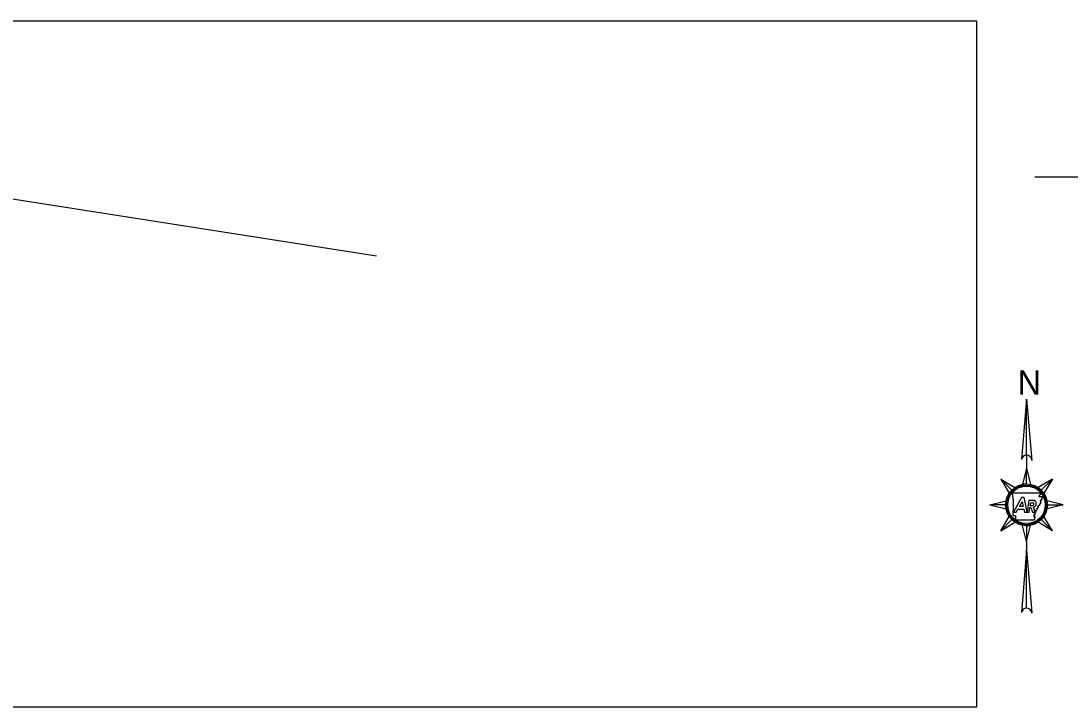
# Model space of a CAD drawing. Extents: x 1096785 to 1382432, y 216169 to 341661.
# Drawn here: x 1178500 to 1204876, y 267368 to 284619 of the extents above; entities that cross this region are included whole.
import ezdxf

# ---------------------------------------------------------------- set-up
doc = ezdxf.new("R2010")
doc.units = 0
for name, color, linetype in [('1', 7, 'Continuous'), ('15', 7, 'Continuous'), ('7', 7, 'Continuous')]:
    doc.layers.add(name, color=color, linetype=linetype)

msp = doc.modelspace()

# ---------------------------------------------------------------- linework, layer by layer
at = {"layer": '1'}
for p, q in [((1169119.475087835, 281573.9332302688), (1187439.3608533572, 278716.3904419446)), ((1203994.739436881, 280695.88328606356), (1218829.6940148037, 280695.88328606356))]:
    msp.add_line(p, q, dxfattribs=at)
at = {"layer": '15'}
for p, q in [((1203782.268836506, 275106.50879252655), (1203652.922527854, 273593.1569813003)), ((1203782.268836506, 275106.50879252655), (1203913.518836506, 273570.88379252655)), ((1203782.268836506, 273702.13379252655), (1203782.268836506, 275106.50879252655)), ((1203782.268836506, 273702.13379252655), (1203782.268836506, 273370.33467056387)), ((1203913.518836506, 273570.88379252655), (1203911.6151451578, 273593.1569813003)), ((1203782.268836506, 273370.33467056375), (1203680.0343561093, 272966.53429044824)), ((1203782.268836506, 272976.58467056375), (1203782.268836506, 273370.33467056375)), ((1203411.0377763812, 272822.81573068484), (1203132.6144812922, 273101.2390257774)), ((1203132.6144812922, 273101.2390257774), (1203345.853773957, 272743.41834439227)), ((1204431.9231917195, 273101.2390257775), (1204074.1025103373, 272887.9997331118)), ((1204153.4998966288, 272822.8157306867), (1204431.9231917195, 273101.2390257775)), ((1204701.018836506, 272451.58467056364), (1204297.2184563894, 272553.81915095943)), ((1203257.268836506, 272451.58467056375), (1202863.518836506, 272451.58467056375)), ((1202863.518836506, 272451.58467056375), (1203267.3192166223, 272349.3501901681)), ((1204307.268836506, 272451.58467056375), (1204701.018836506, 272451.58467056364)), ((1203411.3129541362, 272080.07863651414), (1203132.6144812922, 271801.9303153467)), ((1203132.6144812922, 271801.9303153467), (1203490.4351626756, 272015.16960801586)), ((1203782.268836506, 271532.83467056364), (1203884.5033169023, 271936.63505067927)), ((1204153.4998966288, 272080.3536104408), (1204431.9231917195, 271801.9303153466)), ((1204153.4998966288, 272080.3536104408), (1204431.9231917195, 271801.9303153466)), ((1204431.9231917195, 271801.9303153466), (1204218.683899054, 272159.7509967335)), ((1203782.268836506, 271926.58467056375), (1203782.268836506, 271532.83467056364)), ((1203782.268836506, 271532.83467056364), (1203782.268836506, 271313.3837925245)), ((1203782.268836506, 271313.38379252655), (1203652.7995840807, 269746.8058381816)), ((1203782.268836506, 271313.38379252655), (1203911.7380889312, 269746.8058381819)), ((1203782.268836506, 269856.50879252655), (1203782.268836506, 271313.38379252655)), ((1203913.518836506, 269725.25879252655), (1203911.7380889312, 269746.8058381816))]:
    msp.add_line(p, q, dxfattribs=at)
for points in [[(1203782.268836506, 273370.33467056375), (1203884.5033169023, 272966.53429044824)], [(1203132.6144812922, 273101.2390257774), (1203490.435162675, 272887.9997331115)], [(1204431.9231917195, 273101.2390257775), (1204218.6838990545, 272743.41834439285)], [(1203423.8189762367, 272752.09738259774), (1203628.6294798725, 272751.99966309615), (1203808.5226136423, 272752.40534711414), (1204020.6156765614, 272755.58123113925), (1204118.8695142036, 272757.94722772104)], [(1203423.8189762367, 272752.09738259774), (1203450.0142738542, 272541.49555531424), (1203446.4085333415, 272433.6176597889)], [(1202863.518836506, 272451.58467056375), (1203267.3192166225, 272553.81915096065)], [(1203987.6870217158, 272557.19032146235), (1203844.101783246, 272557.1903214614), (1203795.4400305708, 272277.4364814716), (1203719.3881850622, 272633.50112970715), (1203657.9441271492, 272633.50112970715), (1203451.1812406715, 272267.65591283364)], [(1203603.2809752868, 272411.25397802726), (1203670.9099577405, 272530.91636121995), (1203696.4686452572, 272411.25397802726), (1203603.2809752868, 272411.25397802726)], [(1203936.8481913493, 272427.4251297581), (1203875.2653858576, 272427.4251297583), (1203888.8550725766, 272505.55151926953), (1203956.2779650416, 272505.5515192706)], [(1204088.5679667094, 272659.0817359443), (1204184.801997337, 272663.8403798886)], [(1203446.4085333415, 272433.6176597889), (1203438.6921005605, 272197.82492770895)], [(1203451.1812406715, 272267.65591283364), (1203522.1243847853, 272267.65591283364), (1203565.5095687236, 272344.4214402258), (1203710.743406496, 272344.4214402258), (1203727.13975491, 272267.65591283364), (1203847.4743459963, 272267.65591283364), (1203867.713570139, 272384.010140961), (1203892.5938087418, 272384.010140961), (1203935.5005806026, 272267.6559128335), (1203998.5718803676, 272267.65591283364), (1203953.3761990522, 272390.21718664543)], [(1204701.018836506, 272451.58467056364), (1204297.2184563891, 272349.3501901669)], [(1203132.6144812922, 271801.9303153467), (1203345.853773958, 272159.75099673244)], [(1203508.726391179, 272177.6754611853), (1203508.9736842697, 272074.9500488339), (1203973.3886202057, 272074.2645316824)], [(1203782.268836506, 271532.83467056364), (1203680.0343561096, 271936.6350506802)], [(1204431.9231917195, 271801.9303153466), (1204074.1025103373, 272015.16960801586)]]:
    msp.add_lwpolyline(points, dxfattribs=at)
for radius in [525.0000000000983, 498.7500000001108, 472.5000000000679]:
    msp.add_circle((1203782.268836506, 272451.58467056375), radius, dxfattribs=at)
for centre, radius, start, end in [((1203782.268836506, 273570.88379252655), 131.25, 89.99999999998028, 170.22959486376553), ((1203782.268836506, 273570.88379252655), 131.25, 9.7704051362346, 89.99999999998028), ((1203782.268836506, 272451.58467056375), 525.0000000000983, 135.000000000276, 146.22908827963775), ((1203782.268836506, 272451.58467056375), 525.0000000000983, 89.99999999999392, 101.22908827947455), ((1203782.268836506, 272451.58467056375), 525.0000000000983, 44.999999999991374, 56.22908827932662), ((1203782.268836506, 272451.58467056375), 525.0000000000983, 0, 11.229088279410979), ((1203782.268836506, 272451.58467056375), 525.0000000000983, 180, 191.22908827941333), ((1203782.268836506, 272451.58467056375), 525.0000000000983, 225.0424551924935, 236.22908827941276), ((1203782.268836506, 272451.58467056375), 525.0000000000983, 269.99999999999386, 281.22908827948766), ((1203782.268836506, 272451.58467056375), 525.0000000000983, 315.0000000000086, 326.2290882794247), ((1203782.268836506, 269725.25879252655), 131.25, 89.9999999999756, 170.55109660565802), ((1203782.268836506, 269725.25879252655), 131.25, 9.448903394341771, 89.99999999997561)]:
    msp.add_arc(centre, radius, start, end, dxfattribs=at)
for centre, major_axis, ratio, start_param, end_param in [((1203922.0879920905, 272472.59841424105), (1.5880278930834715e-10, 47.53230592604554), 0.9980982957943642, 3.457965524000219, 5.478416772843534), ((1203934.3064864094, 272481.1759419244), (1.931741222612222e-10, 92.94372588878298), 0.9980982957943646, 3.3486344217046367, 5.670060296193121)]:
    msp.add_ellipse(centre, major_axis=major_axis, ratio=ratio, start_param=start_param, end_param=end_param, dxfattribs=at)
for points in [[(1204118.8695142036, 272757.94722772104), (1204119.584739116, 272752.40534711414), (1204121.2950595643, 272749.48412605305), (1204121.580853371, 272744.102150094), (1204123.8168567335, 272741.8012998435), (1204127.4255588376, 272739.5907661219), (1204130.6921968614, 272735.91888155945), (1204131.5332895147, 272731.68733072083), (1204130.477481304, 272727.1463347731), (1204130.3205168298, 272722.1419114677), (1204129.7296788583, 272717.8777874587), (1204128.9492988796, 272714.0489594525), (1204125.8055670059, 272710.78572010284), (1204123.104593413, 272708.5115206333), (1204120.3947350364, 272705.83904013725), (1204118.37196644, 272703.1621178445), (1204115.1704834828, 272700.0217681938), (1204111.8683063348, 272696.88141853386), (1204109.1317936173, 272694.1097379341), (1204106.455993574, 272690.56370425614), (1204105.2106433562, 272686.6741716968), (1204102.4415531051, 272683.8462283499), (1204100.0174885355, 272681.32476890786), (1204096.9359501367, 272677.8409203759), (1204095.5706553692, 272674.5421466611), (1204092.7067941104, 272670.56377819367), (1204091.9589916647, 272666.80305771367), (1204090.0606100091, 272663.68639763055), (1204089.902164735, 272663.1563433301)], [(1204135.0501822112, 272541.90420053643), (1204135.547729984, 272538.3581668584), (1204133.366516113, 272534.3102102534), (1204132.5283850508, 272530.4547314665), (1204132.9667009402, 272526.4112166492), (1204128.9492988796, 272524.32801440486), (1204125.3405967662, 272521.7739817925), (1204127.4255588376, 272518.7580024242), (1204131.2859964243, 272516.08256072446), (1204135.0501822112, 272513.8764687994), (1204137.3839181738, 272511.60226932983), (1204138.0665655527, 272506.4734757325), (1204138.8173295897, 272503.20283339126), (1204139.9027537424, 272498.601132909), (1204140.3677239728, 272495.48743402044), (1204138.287204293, 272491.6956209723), (1204135.547729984, 272490.8235483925), (1204132.716446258, 272491.7222717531), (1204129.5120017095, 272492.0361586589), (1204126.8687792, 272489.5176604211), (1204124.8445298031, 272486.0308506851), (1204123.104593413, 272482.3323153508), (1204121.580853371, 272479.37704051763), (1204120.1504035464, 272476.07530560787), (1204117.5634513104, 272472.256841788), (1204114.019904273, 272471.6646023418), (1204110.0025022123, 272470.5704399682), (1204107.513282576, 272467.8076429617), (1204107.9812144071, 272463.0786109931), (1204110.2527568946, 272460.0270972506), (1204112.023790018, 272456.0487287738), (1204113.2099083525, 272452.62262358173), (1204112.5864928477, 272448.33036820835), (1204110.8110173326, 272445.12487220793), (1204108.6372074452, 272443.2918911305), (1204107.513282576, 272439.15213740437), (1204105.8962523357, 272436.1687311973), (1204104.3399347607, 272435.0760494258), (1204101.415360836, 272435.3914169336), (1204098.0569134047, 272436.1391192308), (1204095.3174390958, 272435.79413975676), (1204092.7067941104, 272434.3609202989), (1204089.902164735, 272435.23299287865), (1204087.1997103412, 272438.25193345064), (1204084.8333968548, 272440.6149688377), (1204082.2494062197, 272441.4529876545), (1204079.60470291, 272440.08491452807), (1204079.2330228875, 272435.9510832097), (1204080.5405665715, 272431.56258891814), (1204081.6289523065, 272425.68757362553), (1204080.5405665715, 272422.231856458), (1204080.1333474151, 272416.3849725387)], [(1204184.801997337, 272663.8403798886), (1204189.1214819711, 272659.3911810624), (1204190.8021864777, 272655.57123664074), (1204193.7563763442, 272653.51468516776), (1204196.900108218, 272652.3953526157), (1204199.2338441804, 272649.40898521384), (1204200.9145486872, 272646.2701161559), (1204200.0719752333, 272643.4392116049), (1204196.4321763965, 272643.18899043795), (1204192.5125069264, 272642.50347327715), (1204188.7808986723, 272642.7240824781), (1204185.6667827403, 272640.07825275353), (1204188.5336055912, 272636.74690587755), (1204192.2030203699, 272633.45109336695), (1204193.1684999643, 272630.18489282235), (1204191.1146346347, 272626.8254145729), (1204187.1001941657, 272625.0531380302), (1204183.11833123, 272623.5592140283), (1204179.6044001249, 272620.53879286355), (1204177.953311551, 272617.65014496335), (1204174.1565482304, 272616.3131644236), (1204170.0221632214, 272615.159778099), (1204166.505270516, 272614.78962844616), (1204162.3930974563, 272613.9767798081), (1204158.476389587, 272612.0534822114), (1204156.9200720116, 272608.90721016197), (1204157.358387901, 272604.05824969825), (1204157.2310393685, 272599.2063280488), (1204161.3698667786, 272597.5228874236), (1204165.104436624, 272597.3689051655), (1204168.618367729, 272595.5951480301), (1204168.2141101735, 272592.82642862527), (1204165.6301195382, 272589.12493209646), (1204162.3930974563, 272586.4494903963), (1204159.3470981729, 272585.0784560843), (1204156.3603307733, 272582.2830859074), (1204157.358387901, 272579.73201449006), (1204160.1274781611, 272577.95085436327), (1204161.8052210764, 272574.96744815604), (1204161.5875439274, 272572.44598872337), (1204158.6318732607, 272570.45902537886), (1204155.2423290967, 272571.23633965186), (1204152.9085931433, 272574.44035505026), (1204150.1705996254, 272575.34055900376), (1204147.6488024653, 272576.4939453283), (1204145.0381574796, 272574.8149465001), (1204145.0381574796, 272571.23633965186), (1204143.8846166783, 272567.44008480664), (1204144.8175187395, 272564.3619202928), (1204145.9384820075, 272560.31692488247), (1204145.7800367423, 272557.3290768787), (1204144.8175187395, 272552.91245122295), (1204142.6111313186, 272548.4632523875), (1204140.0597182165, 272547.09814046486), (1204139.220106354, 272551.97967409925), (1204138.6899810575, 272555.8677260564), (1204137.0714700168, 272558.2041106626), (1204135.0501822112, 272558.35365112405), (1204132.3743821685, 272556.3962997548), (1204129.5120017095, 272553.41289354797), (1204125.7478159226, 272550.29919466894), (1204123.692469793, 272547.09814046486), (1204124.7823363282, 272543.2722736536), (1204127.4862715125, 272542.18107247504), (1204129.7296788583, 272542.9583867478), (1204130.9424515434, 272545.6027358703), (1204132.9667009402, 272545.84999584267), (1204135.0501822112, 272541.90420053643)], [(1203992.7707711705, 272248.7782483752), (1203991.4321307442, 272245.8821974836), (1203990.0342584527, 272240.7504426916), (1203990.3763225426, 272236.52185305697), (1203992.3679944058, 272232.84996849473), (1203995.3547618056, 272230.7963782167), (1203998.745786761, 272227.90328852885), (1203998.433338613, 272223.51923603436), (1203996.477205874, 272221.743998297), (1203992.0599886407, 272222.89738462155), (1203988.6363861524, 272224.38982802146), (1203985.8317567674, 272223.5488480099), (1203981.820277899, 272221.61814742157), (1203978.988994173, 272221.18581262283), (1203979.1459586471, 272215.1790240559), (1203982.9101444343, 272210.8897298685), (1203986.4551722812, 272210.8897298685), (1203990.311167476, 272210.3596755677), (1203991.7120013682, 272205.8808647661), (1203989.3812270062, 272202.0535173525), (1203985.6496187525, 272200.1257779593), (1203980.887375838, 272202.5213865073), (1203977.4356381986, 272204.82223675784), (1203973.9513230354, 272207.06090186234), (1203969.6540503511, 272208.3060852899), (1203967.320314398, 272207.7138458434), (1203966.1726967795, 272202.5213865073), (1203968.1006943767, 272197.5154825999), (1203971.4265642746, 272194.2463208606), (1203974.5391994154, 272189.9851580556), (1203973.9513230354, 272186.81371582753), (1203971.7404932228, 272185.877977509), (1203967.5379915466, 272184.9762929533), (1203965.3019881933, 272183.8229066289), (1203964.6163792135, 272182.7672398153), (1203965.9875971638, 272178.4735038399), (1203966.9797311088, 272173.7770450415), (1203966.9797311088, 272170.07554851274), (1203965.7343808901, 272167.02995715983), (1203963.4658000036, 272161.86266800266), (1203963.6834771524, 272158.6290406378), (1203965.3019881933, 272157.0433195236), (1203967.1648307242, 272157.47565431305), (1203969.6540503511, 272159.34416976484), (1203971.3673324, 272161.3044823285), (1203972.7681662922, 272163.88516571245), (1203975.3195793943, 272166.0942188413), (1203978.6158333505, 272164.09985250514), (1203979.4865419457, 272160.1821885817), (1203977.4978316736, 272156.8227103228), (1203974.8516475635, 272155.26808178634), (1203971.617587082, 272153.9947669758), (1203969.0365580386, 272151.31636409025), (1203969.7813988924, 272147.8917394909), (1203971.7404932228, 272146.15203612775), (1203976.3768683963, 272147.02558930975), (1203979.5813129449, 272148.48545953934), (1203981.352346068, 272150.1985121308), (1203983.5009824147, 272152.3113263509), (1203984.5612330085, 272154.51741828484), (1203986.302650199, 272156.8227103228), (1203989.1635498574, 272157.47565431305), (1203990.5318062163, 272155.51534174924), (1203990.0342584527, 272151.31636409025), (1203988.2928412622, 272147.2121447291), (1203985.8643343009, 272143.7282961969), (1203983.221111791, 272141.3622996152), (1203980.0166672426, 272136.1653984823), (1203980.669698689, 272131.4393277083), (1203981.820277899, 272127.3054963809), (1203983.5631758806, 272124.28655580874), (1203986.7676204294, 272125.0298163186), (1203990.0342584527, 272125.4014465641), (1203992.0599886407, 272123.72392833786), (1203991.8704466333, 272120.11570952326), (1203989.2257433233, 272116.75623126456), (1203986.9852975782, 272113.42784558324), (1203985.6496187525, 272108.946073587), (1203986.2063983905, 272105.6206491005), (1203986.2063983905, 272102.8489685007), (1203985.1491093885, 272099.6153411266), (1203983.31588279, 272097.93782290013), (1203978.6158333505, 272097.93782290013), (1203973.66849082, 272098.49748917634), (1203971.0874617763, 272097.00504577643), (1203971.617587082, 272092.6831784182), (1203974.5391994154, 272089.5369063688), (1203976.5027361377, 272087.9215732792), (1203979.4865419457, 272084.2807812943), (1203980.7940856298, 272081.38917219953), (1203980.389828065, 272078.92841731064), (1203978.550678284, 272076.6601402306), (1203973.3886202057, 272074.2645316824)], [(1204009.791051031, 272296.40762514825), (1204009.5407963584, 272296.1514815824), (1204007.2396379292, 272293.3205770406), (1204008.4524106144, 272288.8743394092), (1204013.3982723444, 272287.16128680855), (1204015.734969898, 272282.99488231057), (1204015.7645858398, 272279.1038691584), (1204014.240845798, 272273.9114098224), (1204011.8774939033, 272271.3914309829), (1204007.519508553, 272270.4556926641), (1204004.0026158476, 272269.8057098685), (1204003.475452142, 272264.01508869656), (1204001.979847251, 272261.0346436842), (1203999.339586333, 272260.1596099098), (1203995.5739197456, 272262.05773732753), (1203993.238702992, 272263.0260488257), (1203990.3763225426, 272264.30084422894), (1203986.9852975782, 272266.38108527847), (1203984.1865913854, 272266.00945502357), (1203985.0572999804, 272260.4098310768), (1203985.2764579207, 272260.1596099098), (1203988.2928412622, 272255.9932054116), (1203991.2796086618, 272252.69443170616), (1203992.7707711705, 272248.7782483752)], [(1204080.1333474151, 272416.3849725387), (1204075.5310305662, 272413.02549428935), (1204073.6356105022, 272409.54016514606), (1204062.3089948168, 272410.44184970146), (1204062.6791940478, 272406.58340971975), (1204058.6706767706, 272404.4054491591), (1204055.0915905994, 272401.82772697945), (1204057.2046878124, 272398.8383983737), (1204060.911122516, 272395.9778818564), (1204064.736020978, 272393.9864767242), (1204067.1319504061, 272391.77594299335), (1204067.6591141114, 272386.64418820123), (1204068.282529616, 272383.25509797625), (1204069.683363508, 272378.74371400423), (1204070.145372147, 272375.51008663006), (1204067.814597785, 272371.776016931), (1204065.2661462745, 272370.9987026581), (1204062.4319009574, 272371.89890662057), (1204059.2304180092, 272372.17873975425), (1204056.5516563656, 272369.627668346), (1204054.527406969, 272366.08163466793), (1204052.787470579, 272362.4423232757), (1204051.3570207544, 272359.45743647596), (1204049.862896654, 272356.1912359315), (1204047.1574806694, 272352.36388851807), (1204043.7323973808, 272351.74203710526), (1204039.5980123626, 272350.68637029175), (1204037.2642764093, 272347.97835543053), (1204037.6670531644, 272343.3115085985), (1204039.8764021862, 272340.0749200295), (1204041.6814936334, 272336.1883486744), (1204042.9549789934, 272332.6719269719), (1204042.3315634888, 272328.4729493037), (1204040.559049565, 272325.24080253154), (1204038.3526621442, 272323.369325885), (1204037.2642764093, 272319.265106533), (1204035.5509943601, 272316.21655398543), (1204034.0583510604, 272315.1579259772), (1204031.1337771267, 272315.471812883), (1204027.7427521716, 272316.15436884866), (1204024.9410843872, 272315.8745357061), (1204022.4222488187, 272314.5094237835), (1204019.6531585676, 272315.31635003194), (1204016.854452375, 272318.36194137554), (1204014.5503323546, 272320.6657528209), (1204012.0004000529, 272321.5659567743), (1204009.388274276, 272320.2304568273), (1204008.9484775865, 272315.96929402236), (1204010.1612502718, 272311.6444654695), (1204011.2570399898, 272305.8286741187), (1204010.1612502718, 272302.31225241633), (1204009.791051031, 272296.40762514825)], [(1203438.6921005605, 272197.82492770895), (1203440.3802090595, 272192.9004567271), (1203443.4454586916, 272194.0745714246), (1203445.286089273, 272184.13531294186), (1203449.0843333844, 272183.45275697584), (1203452.7863257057, 272182.7672398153), (1203453.4985890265, 272178.4735038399), (1203460.6937812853, 272180.3790342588), (1203462.1449622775, 272178.109276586), (1203464.6726826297, 272178.0411690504), (1203469.0262255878, 272181.242223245), (1203471.6694481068, 272180.3360968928), (1203475.1567248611, 272181.9277404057), (1203478.01910532, 272179.5913557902), (1203483.8045789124, 272181.1519067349), (1203487.1334104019, 272184.48029241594), (1203491.2100443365, 272181.7071312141), (1203494.694359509, 272182.7938905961), (1203499.9378614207, 272179.0405731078), (1203503.5006588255, 272180.52709411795), (1203505.4227332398, 272178.29731260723), (1203508.726391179, 272177.6754611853)]]:
    msp.add_spline(points, degree=3, dxfattribs=at)
at = {"layer": '7'}
msp.add_lwpolyline([(1169927.3411066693, 284619.108250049), (1202526.8290894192, 284619.108250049), (1202526.8290894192, 267367.98169015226), (1169927.3411066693, 267367.98169015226)], close=True, dxfattribs=at)

# ---------------------------------------------------------------- texts
at = {"layer": '15'}
msp.add_text('N', height=605.7630718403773, dxfattribs=at).set_placement((1203560.923560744, 275225.68543485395))

doc.saveas('drawing.dxf')
